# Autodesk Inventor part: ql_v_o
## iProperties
Created: 2007-11
Part Number: ql_v_o
Document SubType Name: Modeling
Designer: martin
Manufacturer: Standard
Standards Organization: Custom
Author: martin
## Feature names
1. Extrusion2
